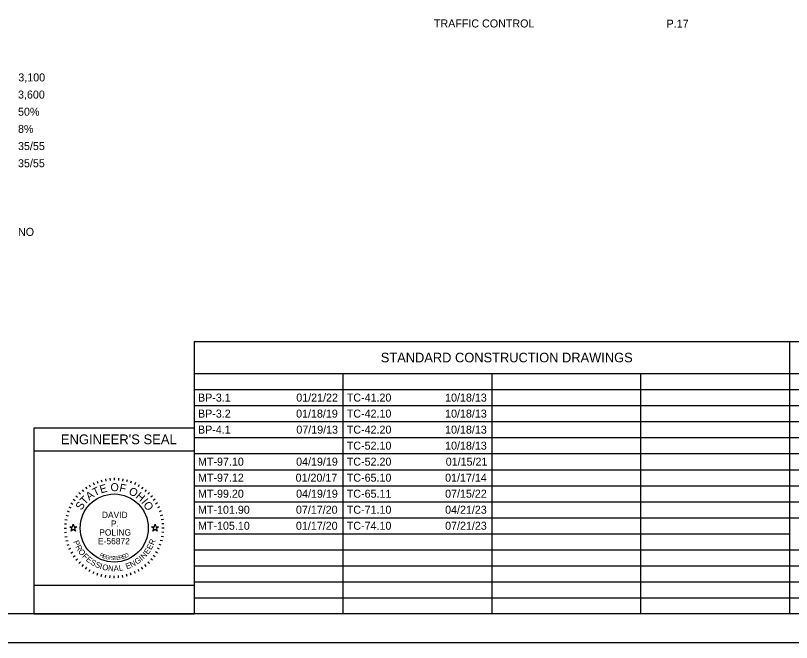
# Model space of a CAD drawing. Extents: x 0 to 34, y 0 to 22.
# Drawn here: x 7.69 to 21.27, y 0 to 10.96 of the extents above; entities that cross this region are included whole.
import ezdxf

# ---------------------------------------------------------------- set-up
doc = ezdxf.new("R2010")
doc.units = 0
for name, color, linetype in [('Default', 7, 'Continuous'), ('SC_Scratch9', 7, 'Continuous'), ('SH_Border', 7, 'Continuous'), ('SH_Cut_Line', 7, 'Continuous'), ('SH_Data', 7, 'Continuous')]:
    doc.layers.add(name, color=color, linetype=linetype)

msp = doc.modelspace()

# ---------------------------------------------------------------- linework, layer by layer
at = {"layer": 'Default'}
for points in [[(8.642, 2.02), (8.689, 2.02), (8.704, 2.065), (8.718, 2.02), (8.765, 2.02), (8.727, 1.992), (8.742, 1.948), (8.704, 1.975), (8.666, 1.948), (8.68, 1.992)], [(10.072, 2.02), (10.119, 2.02), (10.134, 2.065), (10.148, 2.02), (10.195, 2.02), (10.157, 1.992), (10.172, 1.948), (10.134, 1.975), (10.096, 1.948), (10.11, 1.992)]]:
    msp.add_lwpolyline(points, close=True, dxfattribs=at)
at = {"layer": 'SH_Border'}
msp.add_lwpolyline([(0, 0), (34, 0), (34, 22), (0, 22)], close=True, dxfattribs=at)
at = {"layer": 'SH_Cut_Line'}
for p, q in [((10.819, 5.26), (23.6, 5.26)), ((10.819, 5.26), (10.819, 0.5)), ((21.228, 5.26), (21.228, 0.5)), ((10.819, 4.7), (23.6, 4.7)), ((13.421, 4.7), (13.421, 0.5)), ((16.024, 4.7), (16.024, 0.5)), ((18.626, 4.7), (18.626, 0.5)), ((10.819, 4.42), (23.6, 4.42)), ((10.819, 4.14), (23.6, 4.14)), ((10.819, 3.86), (23.6, 3.86)), ((8.019, 0.5), (8.019, 3.75)), ((8.019, 3.75), (10.819, 3.75)), ((10.819, 3.75), (10.819, 0.5)), ((10.819, 3.58), (23.6, 3.58)), ((8.019, 3.35), (10.819, 3.35)), ((10.819, 3.3), (23.6, 3.3)), ((10.819, 3.02), (23.6, 3.02)), ((9.267, 2.862), (9.274, 2.822)), ((9.343, 2.872), (9.346, 2.832)), ((9.419, 2.875), (9.419, 2.835)), ((9.495, 2.872), (9.492, 2.832)), ((9.571, 2.862), (9.564, 2.822)), ((8.917, 2.717), (8.94, 2.684)), ((8.981, 2.758), (9.001, 2.723)), ((9.049, 2.793), (9.066, 2.757)), ((9.12, 2.822), (9.133, 2.785)), ((9.192, 2.845), (9.203, 2.807)), ((9.645, 2.845), (9.635, 2.807)), ((9.718, 2.822), (9.704, 2.785)), ((9.789, 2.793), (9.772, 2.757)), ((9.856, 2.758), (9.836, 2.723)), ((9.921, 2.717), (9.898, 2.684)), ((10.819, 2.74), (23.6, 2.74)), ((8.8, 2.619), (8.828, 2.59)), ((8.856, 2.67), (8.882, 2.64)), ((9.981, 2.67), (9.956, 2.64)), ((10.038, 2.619), (10.009, 2.59)), ((8.702, 2.502), (8.735, 2.479)), ((8.749, 2.562), (8.779, 2.537)), ((10.089, 2.562), (10.058, 2.537)), ((10.136, 2.502), (10.103, 2.479)), ((10.819, 2.46), (23.6, 2.46)), ((8.626, 2.37), (8.662, 2.353)), ((8.661, 2.438), (8.696, 2.418)), ((10.177, 2.438), (10.142, 2.418)), ((10.212, 2.37), (10.176, 2.353)), ((8.574, 2.226), (8.612, 2.216)), ((8.597, 2.299), (8.634, 2.286)), ((10.241, 2.299), (10.203, 2.286)), ((10.264, 2.226), (10.225, 2.216)), ((10.819, 2.18), (21.228, 2.18)), ((21.228, 2.18), (23.6, 2.18)), ((8.547, 2.076), (8.587, 2.073)), ((8.557, 2.152), (8.596, 2.145)), ((10.281, 2.152), (10.241, 2.145)), ((10.29, 2.076), (10.251, 2.073)), ((8.544, 2), (8.584, 2)), ((8.547, 1.924), (8.587, 1.927)), ((10.29, 1.924), (10.251, 1.927)), ((10.294, 2), (10.254, 2)), ((8.557, 1.848), (8.596, 1.855)), ((8.574, 1.774), (8.612, 1.784)), ((10.264, 1.774), (10.225, 1.784)), ((10.281, 1.848), (10.241, 1.855)), ((10.819, 1.9), (21.228, 1.9)), ((8.597, 1.701), (8.634, 1.714)), ((8.626, 1.63), (8.662, 1.647)), ((10.212, 1.63), (10.176, 1.647)), ((10.241, 1.701), (10.203, 1.714)), ((8.661, 1.563), (8.696, 1.583)), ((8.702, 1.498), (8.735, 1.521)), ((10.136, 1.498), (10.103, 1.521)), ((10.177, 1.563), (10.142, 1.583)), ((10.819, 1.62), (21.228, 1.62)), ((21.228, 1.62), (23.6, 1.62)), ((8.749, 1.438), (8.779, 1.463)), ((8.8, 1.381), (8.828, 1.41)), ((8.856, 1.33), (8.882, 1.36)), ((9.981, 1.33), (9.956, 1.36)), ((10.038, 1.381), (10.009, 1.41)), ((10.089, 1.438), (10.058, 1.463)), ((8.917, 1.283), (8.94, 1.316)), ((8.981, 1.242), (9.001, 1.277)), ((9.049, 1.207), (9.066, 1.243)), ((9.789, 1.207), (9.772, 1.243)), ((9.856, 1.242), (9.836, 1.277)), ((9.921, 1.283), (9.898, 1.316)), ((10.819, 1.34), (23.6, 1.34)), ((9.12, 1.178), (9.133, 1.215)), ((9.192, 1.155), (9.203, 1.193)), ((9.267, 1.138), (9.274, 1.178)), ((9.343, 1.128), (9.346, 1.168)), ((9.419, 1.125), (9.419, 1.165)), ((9.495, 1.128), (9.492, 1.168)), ((9.571, 1.138), (9.564, 1.178)), ((9.645, 1.155), (9.635, 1.193)), ((9.718, 1.178), (9.704, 1.215)), ((10.819, 1.06), (23.6, 1.06)), ((10.819, 0.78), (23.6, 0.78)), ((8.019, 0.5), (10.819, 0.5))]:
    msp.add_line(p, q, dxfattribs=at)
msp.add_lwpolyline([(8.019, 0.5), (8.019, 1), (10.819, 1), (10.819, 0.5)], close=True, dxfattribs=at)
msp.add_circle((9.419, 2), 0.595, dxfattribs=at)
at = {"layer": 'SH_Data'}
msp.add_lwpolyline([(1.5, 21.5), (33.5, 21.5), (33.5, 0.5), (1.5, 0.5)], close=True, dxfattribs=at)

# ---------------------------------------------------------------- texts
at = {"layer": 'SC_Scratch9'}
for s, p in [('3,100', (7.742, 9.806)), ('3,600', (7.737, 9.506)), ('50%', (7.737, 9.206)), ('8%', (7.737, 8.906)), ('35/55', (7.737, 8.606)), ('35/55', (7.737, 8.306)), ('NO', (7.737, 7.106))]:
    msp.add_text(s, height=0.14, dxfattribs=at).set_placement(p)
at = {"layer": 'SH_Cut_Line'}
for s, height, p in [('TRAFFIC CONTROL', 0.14, (15.011, 10.749)), ('P.17', 0.14, (19.081, 10.745)), ('STANDARD CONSTRUCTION DRAWINGS', 0.168, (14.082, 4.896)), ('BP-3.1', 0.14, (10.885, 4.21)), ('01/21/22', 0.14, (12.604, 4.21)), ('TC-41.20', 0.14, (13.487, 4.21)), ('10/18/13', 0.14, (15.207, 4.21)), ('BP-3.2', 0.14, (10.885, 3.93)), ('01/18/19', 0.14, (12.601, 3.93)), ('TC-42.10', 0.14, (13.487, 3.93)), ('10/18/13', 0.14, (15.207, 3.93)), ('BP-4.1', 0.14, (10.885, 3.65)), ('07/19/13', 0.14, (12.605, 3.65)), ('TC-42.20', 0.14, (13.487, 3.65)), ('10/18/13', 0.14, (15.207, 3.65)), ("ENGINEER'S SEAL", 0.17, (8.486, 3.465)), ('TC-52.10', 0.14, (13.487, 3.37)), ('10/18/13', 0.14, (15.207, 3.37)), ('MT-97.10', 0.14, (10.885, 3.09)), ('04/19/19', 0.14, (12.601, 3.09)), ('TC-52.20', 0.14, (13.487, 3.09)), ('01/15/21', 0.14, (15.218, 3.09)), ('MT-97.12', 0.14, (10.885, 2.81)), ('01/20/17', 0.14, (12.592, 2.81)), ('TC-65.10', 0.14, (13.487, 2.81)), ('01/17/14', 0.14, (15.207, 2.81)), ('MT-99.20', 0.14, (10.885, 2.53)), ('04/19/19', 0.14, (12.601, 2.53)), ('TC-65.11', 0.14, (13.487, 2.53)), ('07/15/22', 0.14, (15.207, 2.53)), ('MT-101.90', 0.14, (10.885, 2.25)), ('07/17/20', 0.14, (12.598, 2.25)), ('TC-71.10', 0.14, (13.487, 2.25)), ('04/21/23', 0.14, (15.207, 2.25)), ('DAVID', 0.11, (9.204, 2.175)), ('P.', 0.11, (9.361, 2.022)), ('MT-105.10', 0.14, (10.885, 1.97)), ('01/17/20', 0.14, (12.598, 1.97)), ('TC-74.10', 0.14, (13.487, 1.97)), ('07/21/23', 0.14, (15.207, 1.97)), ('POLING', 0.11, (9.158, 1.868)), ('E-56872', 0.11, (9.136, 1.715))]:
    msp.add_text(s, height=height, dxfattribs=at).set_placement(p)
for s, height, rotation, p in [('T', 0.14, 25.7167, (9.08, 2.552)), ('E', 0.14, 15.7571, (9.187, 2.604)), ('O', 0.14, 359.7812, (9.354, 2.644)), ('F', 0.14, 347.4362, (9.5, 2.642)), ('A', 0.14, 36.4747, (8.982, 2.478)), ('O', 0.14, 332.2586, (9.659, 2.602)), ('H', 0.14, 319.9136, (9.782, 2.536)), ('S', 0.14, 57.1924, (8.847, 2.301)), ('T', 0.14, 46.4344, (8.907, 2.396)), ('I', 0.14, 308.367, (9.885, 2.448)), ('O', 0.14, 303.1491, (9.921, 2.409)), ('P', 0.1, 291.494, (8.701, 1.762)), ('R', 0.1, 69.2322, (10.111, 1.695)), ('R', 0.1, 298.7311, (8.738, 1.672)), ('E', 0.1, 54.758, (10.012, 1.531)), ('E', 0.1, 61.9951, (10.066, 1.61)), ('O', 0.1, 306.4666, (8.784, 1.588)), ('F', 0.1, 314.7068, (8.853, 1.498)), ('E', 0.1, 321.4393, (8.917, 1.435)), ('R', 0.07, 334.487, (9.156, 1.505)), ('E', 0.07, 341.04, (9.209, 1.48)), ('G', 0.07, 347.4752, (9.26, 1.462)), ('I', 0.07, 353.7858, (9.328, 1.447)), ('S', 0.07, 356.8926, (9.355, 1.443)), ('T', 0.07, 3.0061, (9.405, 1.439)), ('E', 0.07, 6.0117, (9.458, 1.441)), ('R', 0.07, 11.9184, (9.511, 1.447)), ('E', 0.07, 17.6836, (9.569, 1.46)), ('D', 0.07, 23.3052, (9.62, 1.477)), ('I', 0.1, 43.287, (9.906, 1.421)), ('N', 0.1, 47.0224, (9.939, 1.451)), ('S', 0.1, 328.6764, (8.993, 1.375)), ('S', 0.1, 335.9134, (9.075, 1.327)), ('I', 0.1, 343.1505, (9.159, 1.29)), ('O', 0.1, 346.8859, (9.203, 1.275)), ('E', 0.1, 20.0742, (9.64, 1.277)), ('N', 0.1, 27.3113, (9.723, 1.308)), ('G', 0.1, 35.0469, (9.817, 1.357)), ('N', 0.1, 355.1261, (9.308, 1.252)), ('A', 0.1, 2.8617, (9.411, 1.244)), ('L', 0.1, 10.0987, (9.508, 1.249))]:
    msp.add_text(s, height=height, rotation=rotation, dxfattribs=at).set_placement(p)

doc.saveas('drawing.dxf')
